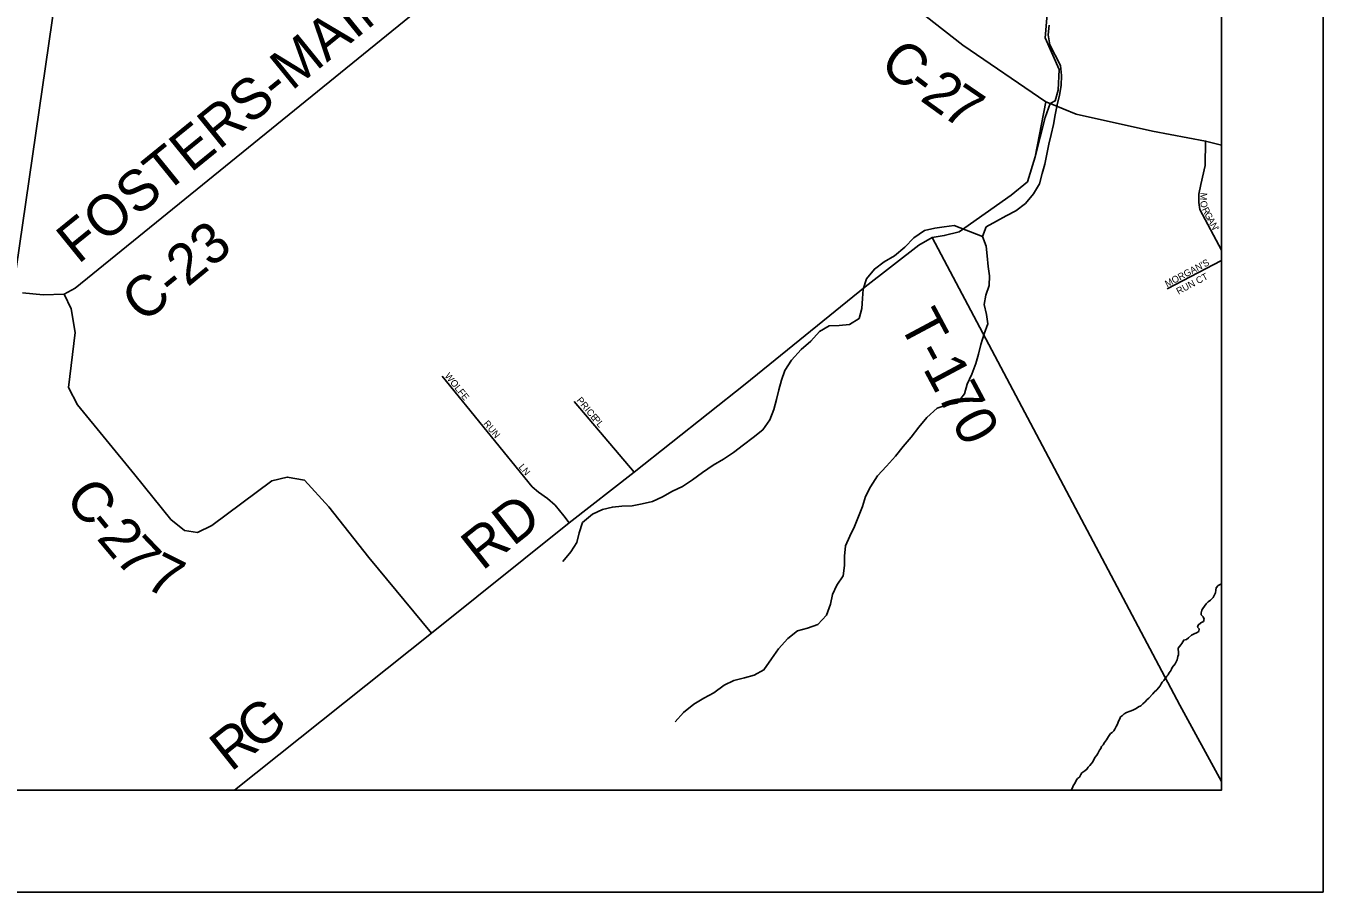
# Model space of a CAD drawing. Extents: x 0 to 34, y -4 to 22.
# Drawn here: x 7.725 to 9, y 14 to 14.851 of the extents above; entities that cross this region are included whole.
import ezdxf

# ---------------------------------------------------------------- set-up
doc = ezdxf.new("R2010")
doc.units = 0
for name, color, linetype in [('GM_X_County_Road', 7, 'Continuous'), ('GM_X_County_Road_Text', 7, 'Continuous'), ('GM_X_Minor_River', 7, 'Continuous'), ('GM_X_Township', 7, 'Continuous'), ('GM_X_Township_Road', 7, 'Continuous'), ('GM_X_Township_Road_Text', 7, 'Continuous'), ('GM_X_Township_Subdivision', 7, 'Continuous'), ('GM_X_Township_Subdivision_Text', 7, 'Continuous'), ('SH_Data', 7, 'Continuous'), ('SN_P_Text', 7, 'Continuous')]:
    doc.layers.add(name, color=color, linetype=linetype)

msp = doc.modelspace()

# ---------------------------------------------------------------- linework, layer by layer
at = {"layer": 'GM_X_County_Road'}
for points in [[(8.2649, 15.3373), (8.4177, 15.1037), (8.4949, 14.9957), (8.5119, 14.9757), (8.5524, 14.9258), (8.5844, 14.8809), (8.6458, 14.8325), (8.7276, 14.7769)], [(7.7213, 14.589), (7.7418, 14.5871), (7.7622, 14.5878), (7.773, 14.5936), (8.3575, 15.0682), (8.3759, 15.0816), (8.3979, 15.0945), (8.4177, 15.1037)], [(7.9297, 14.1), (8.1235, 14.2546), (8.2588, 14.3629), (8.3226, 14.4128), (8.4319, 14.4993), (8.5498, 14.5949), (8.6027, 14.6358), (8.6157, 14.6436), (8.6275, 14.6453), (8.6423, 14.649), (8.6935, 14.685), (8.7093, 14.6983), (8.717, 14.7228), (8.7276, 14.7769)], [(8.7276, 14.7769), (8.7316, 14.7752), (8.7573, 14.7647), (8.8324, 14.7481), (8.8845, 14.7382), (8.9, 14.7341)], [(8.1235, 14.2546), (8.0617, 14.329), (8.0225, 14.3788), (7.9987, 14.4048), (7.9817, 14.408), (7.9664, 14.4043), (7.9076, 14.3603), (7.8933, 14.3534), (7.8805, 14.3555), (7.8673, 14.3661), (7.8318, 14.4101), (7.7756, 14.479), (7.7666, 14.4959), (7.773, 14.55), (7.7693, 14.5733), (7.7622, 14.5878)]]:
    msp.add_lwpolyline(points, dxfattribs=at)
at = {"layer": 'GM_X_Minor_River'}
for points in [[(8.363, 14.1674), (8.3712, 14.1766), (8.3815, 14.1847), (8.3912, 14.1905), (8.4009, 14.1959), (8.4112, 14.2033), (8.4207, 14.2079), (8.4312, 14.2107), (8.4406, 14.2132), (8.4503, 14.2184), (8.4577, 14.2292), (8.4645, 14.239), (8.4738, 14.2493), (8.4833, 14.2569), (8.493, 14.2594), (8.5032, 14.263), (8.5119, 14.2722), (8.5158, 14.2829), (8.5178, 14.2925), (8.522, 14.3017), (8.5283, 14.311), (8.5295, 14.3209), (8.5294, 14.3302), (8.5304, 14.3404), (8.5346, 14.3497), (8.5393, 14.3595), (8.5432, 14.3693), (8.5471, 14.3791), (8.5502, 14.3887), (8.5552, 14.3985), (8.562, 14.4091), (8.5708, 14.4186), (8.5797, 14.4284), (8.5871, 14.4379), (8.595, 14.4471), (8.6027, 14.4571), (8.6106, 14.4666), (8.6207, 14.4758), (8.6306, 14.4789), (8.6403, 14.4806), (8.6474, 14.4898), (8.6502, 14.4992), (8.6546, 14.509), (8.6586, 14.5196), (8.6614, 14.5289), (8.6637, 14.5382), (8.6668, 14.5486), (8.6704, 14.5585), (8.669, 14.5678), (8.6667, 14.5775), (8.6685, 14.5868), (8.6719, 14.5964), (8.672, 14.6057), (8.6706, 14.6151), (8.6699, 14.6253), (8.6688, 14.6349), (8.6652, 14.6444), (8.6688, 14.6539), (8.6791, 14.6594), (8.6885, 14.6646), (8.6979, 14.6698), (8.7074, 14.6768), (8.7153, 14.6863), (8.7211, 14.6961), (8.724, 14.7063), (8.7265, 14.7156), (8.7283, 14.7254), (8.7303, 14.7353), (8.7326, 14.7446), (8.7349, 14.7545), (8.7367, 14.7641), (8.7387, 14.7739), (8.741, 14.7835), (8.7425, 14.7928), (8.7427, 14.8027), (8.742, 14.8124), (8.7366, 14.8226), (8.7314, 14.8329), (8.7299, 14.8428), (8.7306, 14.8521)], [(8.6652, 14.6444), (8.6373, 14.6552), (8.6276, 14.6538), (8.6182, 14.6526), (8.608, 14.6504), (8.5977, 14.643), (8.5888, 14.6338), (8.5787, 14.6254), (8.5685, 14.6194), (8.559, 14.6124), (8.5511, 14.6029), (8.5477, 14.5928), (8.5473, 14.5834), (8.5466, 14.5738), (8.544, 14.5639), (8.5343, 14.5579), (8.5244, 14.5568), (8.5145, 14.5567), (8.505, 14.5509), (8.4963, 14.5414), (8.4868, 14.5333), (8.4775, 14.5228), (8.4709, 14.5127), (8.4676, 14.5031), (8.465, 14.4936), (8.4627, 14.4842), (8.4601, 14.4744), (8.456, 14.4643), (8.4491, 14.4545), (8.4396, 14.4469), (8.4301, 14.4398), (8.4204, 14.4322), (8.4104, 14.4257), (8.4004, 14.4195), (8.3898, 14.4124), (8.3801, 14.4053), (8.3701, 14.3988), (8.3604, 14.3942), (8.3506, 14.3884), (8.3409, 14.384), (8.3305, 14.3815), (8.3208, 14.3798), (8.3106, 14.3794), (8.3013, 14.3785), (8.2916, 14.376), (8.2816, 14.3716), (8.2719, 14.3632), (8.2685, 14.3531), (8.2662, 14.3435), (8.2604, 14.3343), (8.2525, 14.325)], [(8.8656, 14.2482), (8.8678, 14.2498), (8.8708, 14.2524), (8.8733, 14.2539), (8.8757, 14.2549), (8.8779, 14.2562), (8.8782, 14.2586), (8.8766, 14.2605), (8.8772, 14.2624), (8.88, 14.2645), (8.8824, 14.266), (8.883, 14.2684), (8.882, 14.2706), (8.8802, 14.2725), (8.8802, 14.2746), (8.8808, 14.277), (8.8819, 14.2789), (8.8833, 14.281), (8.885, 14.2833), (8.8869, 14.2852), (8.8894, 14.287), (8.8918, 14.2896), (8.8929, 14.2914), (8.8943, 14.2941), (8.8947, 14.2967), (8.895, 14.2989), (8.8969, 14.3012), (8.8988, 14.3025), (8.9, 14.3031)], [(8.8602, 14.2429), (8.861, 14.2445), (8.8621, 14.2461), (8.863, 14.2477), (8.8656, 14.2482)], [(8.7523, 14.1), (8.7533, 14.1018), (8.7547, 14.105), (8.7558, 14.1066), (8.7574, 14.1095), (8.7585, 14.1116), (8.7604, 14.1129), (8.7618, 14.1156), (8.7629, 14.1172), (8.7659, 14.1193), (8.7678, 14.1208), (8.7691, 14.1227), (8.7708, 14.1245), (8.7719, 14.1261), (8.7735, 14.128), (8.7743, 14.1298), (8.776, 14.1327), (8.7776, 14.1346), (8.7785, 14.1362), (8.7801, 14.1396), (8.7815, 14.1412), (8.7823, 14.1431), (8.7837, 14.1446), (8.7851, 14.147), (8.7872, 14.1497), (8.7881, 14.1513), (8.7892, 14.1528), (8.7911, 14.1558), (8.7927, 14.1568), (8.7943, 14.1584), (8.7952, 14.1602), (8.7965, 14.1626), (8.7976, 14.1645), (8.7982, 14.1661), (8.7988, 14.1679), (8.8002, 14.1703), (8.801, 14.1722), (8.8029, 14.1735), (8.8045, 14.1751), (8.8069, 14.1764), (8.8102, 14.1779), (8.8129, 14.1789), (8.8148, 14.1797), (8.8164, 14.1805), (8.8185, 14.1821), (8.8207, 14.1831), (8.8229, 14.1849), (8.825, 14.187), (8.8269, 14.1889), (8.8286, 14.1907), (8.8327, 14.1947), (8.834, 14.1965), (8.8365, 14.1989), (8.8381, 14.2007), (8.8397, 14.2028), (8.8408, 14.2047), (8.8417, 14.2063), (8.8433, 14.2079), (8.8447, 14.21), (8.8463, 14.2121), (8.8477, 14.2137), (8.8485, 14.2153), (8.8499, 14.2171), (8.851, 14.219), (8.8518, 14.2206), (8.8546, 14.2245), (8.8565, 14.2282), (8.857, 14.2298), (8.8573, 14.2314), (8.8579, 14.2333), (8.858, 14.2365), (8.8577, 14.2381), (8.8577, 14.2397), (8.8588, 14.2413), (8.8602, 14.2429)]]:
    msp.add_lwpolyline(points, dxfattribs=at)
at = {"layer": 'GM_X_Township'}
for points in [[(3.8794, 14.1), (7.6703, 14.1), (7.7118, 14.5899), (7.7699, 14.9905), (7.8078, 15.2433), (7.8116, 15.2993), (7.8125, 15.3129), (7.8465, 15.6298), (7.8833, 16.0418)], [(7.8833, 16.0418), (7.8465, 15.6298), (7.8125, 15.3129), (7.8116, 15.2993), (7.8078, 15.2433), (7.7699, 14.9905), (7.7118, 14.5899)], [(8.729, 14.8668), (8.7269, 14.8398), (8.7404, 14.8086), (8.7395, 14.7883), (8.7366, 14.7777), (8.7316, 14.7752), (8.7269, 14.7613), (8.717, 14.7228), (8.7093, 14.6983), (8.6935, 14.685), (8.6423, 14.649), (8.6275, 14.6453), (8.6157, 14.6436), (8.6027, 14.6358), (8.5498, 14.5949), (8.4319, 14.4993), (8.3226, 14.4128), (8.2588, 14.3629), (8.1235, 14.2546), (7.9297, 14.1), (8.9, 14.1), (8.9, 14.9923)], [(7.6703, 14.1), (7.9297, 14.1), (8.1235, 14.2546), (8.2588, 14.3629), (8.3226, 14.4128), (8.4319, 14.4993), (8.5498, 14.5949), (8.6027, 14.6358), (8.6157, 14.6436), (8.6275, 14.6453), (8.6423, 14.649), (8.6935, 14.685), (8.7093, 14.6983), (8.717, 14.7228), (8.7269, 14.7613), (8.7316, 14.7752), (8.7366, 14.7777), (8.7395, 14.7883), (8.7404, 14.8086), (8.7269, 14.8398), (8.729, 14.8668)]]:
    msp.add_lwpolyline(points, dxfattribs=at)
at = {"layer": 'GM_X_Township_Road'}
msp.add_lwpolyline([(8.6157, 14.6436), (8.8593, 14.1836), (8.9, 14.1088)], dxfattribs=at)
at = {"layer": 'GM_X_Township_Subdivision'}
msp.add_line((8.8468, 14.593), (8.9, 14.6207), dxfattribs=at)
for points in [[(8.9, 14.6309), (8.8789, 14.6711), (8.8778, 14.6779), (8.8778, 14.6862), (8.8799, 14.6956), (8.8841, 14.7144), (8.8845, 14.7382)], [(8.2588, 14.3629), (8.2535, 14.3698), (8.245, 14.3804), (8.2376, 14.3868), (8.2286, 14.3931), (8.2223, 14.3984), (8.1338, 14.5071)], [(8.2636, 14.4822), (8.3226, 14.4128)]]:
    msp.add_lwpolyline(points, dxfattribs=at)
at = {"layer": 'SH_Data'}
for p, q in [((9, 21), (9, 14)), ((8.9, 20.9), (8.9, 14.1)), ((2.1, 14.1), (8.9, 14.1)), ((2, 14), (9, 14))]:
    msp.add_line(p, q, dxfattribs=at)
at = {"layer": 'SN_P_Text'}
msp.add_lwpolyline([(8.9, 14.1), (8.9, 20.9), (2.1, 20.9), (2.1, 14.1)], close=True, dxfattribs=at)

# ---------------------------------------------------------------- texts
at = {"layer": 'GM_X_County_Road_Text'}
for s, rotation, p in [('FOSTERS-MAINEVILLE', 39.0783, (7.7761, 14.6166)), ('C', 321.6218, (8.5623, 14.8105)), ('2', 324.2353, (8.6027, 14.779)), ('-', 322.8396, (8.5887, 14.7895)), ('7', 325.7459, (8.6236, 14.7639)), ('C-23', 39.4105, (7.8401, 14.5583)), ('C', 308.942, (7.7618, 14.3865)), ('RD', 38.3509, (8.1734, 14.3152)), ('-', 309.1612, (7.7826, 14.3608)), ('2', 310.0293, (7.7934, 14.3476)), ('7', 313.701, (7.8111, 14.3266)), ('7', 333.4873, (7.8402, 14.2999)), ('G', 38.5597, (7.952, 14.1379)), ('R', 38.5617, (7.9263, 14.1175))]:
    msp.add_text(s, height=0.04, rotation=rotation, dxfattribs=at).set_placement(p)
at = {"layer": 'GM_X_Township_Road_Text'}
msp.add_text('T-170', height=0.04, rotation=298.0726, dxfattribs=at).set_placement((8.5824, 14.5594))
at = {"layer": 'GM_X_Township_Subdivision_Text'}
for s, rotation, p in [('M', 266.2089, (8.8795, 14.6877)), ('O', 278.7317, (8.8791, 14.6791)), ('R', 296.1781, (8.8807, 14.6712)), ('G', 298.4198, (8.8831, 14.6662)), ('A', 298.4198, (8.8859, 14.661)), ('N', 298.4352, (8.8887, 14.6558)), ("'", 298.4689, (8.8915, 14.6507)), ("MORGAN'S", 27.9801, (8.8467, 14.5944)), ('RUN CT', 28.0717, (8.8579, 14.5872)), ('WOLFE', 309.036, (8.136, 14.5072)), ('PRICE', 309.8049, (8.2657, 14.4832)), ('RUN', 309.8041, (8.1741, 14.4603)), ('PL', 309.7984, (8.2815, 14.4644)), ('LN', 310.6039, (8.2087, 14.4175))]:
    msp.add_text(s, height=0.00667, rotation=rotation, dxfattribs=at).set_placement(p)

doc.saveas('drawing.dxf')
